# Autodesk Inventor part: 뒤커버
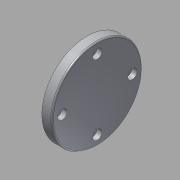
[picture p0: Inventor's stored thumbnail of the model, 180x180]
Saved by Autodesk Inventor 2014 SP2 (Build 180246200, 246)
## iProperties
Created: 2015-09
Part Number: 뒤커버
Material: 알루미늄 6061
Document SubType Name: Modeling
Designer: mduedu
Density: 1 g/cm^3
Appearance: 알루미늄 - 평지
Author: mduedu
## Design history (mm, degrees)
sketch "스케치1"
  geometry: L1 (-15.5, 47)-(-15.5, 78); L2 (-15.5, 78)-(-22.5, 78); L3 (-22.5, 78)-(-22.5, 67); L4 (-25.5, 67)-(-25.5, 47); L5 (-79.5, 39.5)-(-79.5, 54.5) reference; L6 (48.5, 54.5)-(48.5, 39.5) reference; L7 (-79.5, 47)-(48.5, 47); L8 (-22.5, 67)-(-25.5, 67); L9 (-25.5, 47)-(-15.5, 47); 1 further point
  constraints: 14 end point, 4 midpoint, 3 parallel, 1 collinear, 1 point on line, 1 vertical
  dimensions: "d6" = 62 diameter of L2 L7; "d7" = 7 distance of L1.end L2.end; "d8" = 40 diameter of L3.end L7; "d32" = 10 distance between parallel lines of L1 L4
revolve "회전1" sketch "스케치1" stored, may be unused: angle "d4" = 90 deg
sketch "스케치4"
  geometry: C1 r 31 at (0, 0) reference; 2 further points
  constraints: 1 coincident
hole "구멍3" sketch "스케치4" at (0, 0) diameter "d33" = 33; stored, may be unused: countersink angle "d37" = 90 deg, drill point angle "d39" = 0 deg; dims "d34" = 6, "d35" = 4, "d36" = 2, "d38" = 5
fillet "모깎기4" dims "d40" = 1
chamfer "모따기2" distance "d41" = 1; stored, may be unused: second distance "d42" = 2, angle "d43" = 45 deg
sketch "스케치5" dims "d44" = 48
  geometry: C1 r 31 at (0, 0) reference; 6 further points
  constraints: 2 vertical alignment, 1 coincident, 7 other
  dimensions: "d47" = 360 deg dimension on C1.centre point (0, -24) (derived)
sketch "스케치6"
  geometry: 4 further points
hole "구멍4" sketch "스케치6" at (24, 0), (0, 24), (-24, 0), (0, -24) diameter "d49" = 3.4; stored, may be unused: countersink angle "d53" = 90 deg, drill point angle "d55" = 0 deg; dims "d50" = 6, "d51" = 6.5, "d52" = 3.4, "d54" = 8
node "솔리드1"
node "참조1"
node "참조2"
